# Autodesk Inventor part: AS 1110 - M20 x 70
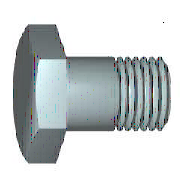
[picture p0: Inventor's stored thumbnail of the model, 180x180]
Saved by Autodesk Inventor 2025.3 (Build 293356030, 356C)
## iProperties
IsCustomPart: 0
Created: 2024-01
Part Number: AS 1110 - M20 x 70
Material: Acero, suave
Description: Pernos y tornillos métricos ISO de precisión de cabeza hexagonal
Document SubType Name: Modeling
Standard: AS 1110
Designer: User
Standards Organization: AS
Language: es-ES
Size Designation: M20 x 70
Categories: <MemberInstance><Categories><Category DisplayName="Fijaciones" InternalName="e4da775c-781d-43d5-af7c-5136215cf5a6" Mnemonic="FSTN"><Category DisplayName="Pernos
Density: 7.85 g/cm^3
Appearance: Semipulido
Author: User
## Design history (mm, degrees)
workplane "Work Plane1"
revolve "Cuerpo" stored, may be unused: angle "d12" = 90 deg
sketch "Boceto2"
  geometry: L1 (0, 17.321)-(15, 8.66); L2 (15, 8.66)-(15, -8.66); L3 (15, -8.66)-(0, -17.321); L4 (0, -17.321)-(-15, -8.66); L5 (-15, -8.66)-(-15, 8.66); L6 (-15, 8.66)-(0, 17.321); 2 further points
  constraints: 12 end point, 1 coincident, 1 vertical, 11 other
  dimensions: "d11" = 30 distance between parallel lines of L5 L2 (= SW)
extrude "Cabeza" join sketch "Boceto2" distance "d3" = 11.7 (= KOH - SD); taper "d4" = 0 deg
revolve "Chaflán1" stored, may be unused: angle "d21" = 90 deg
body "Solid1"
feature "Rosca" dims "d15" = 62.5 (= GEL), "d16" = 0
chamfer "Chaflán2" distance "d6" = 1.53363 (= -0.5 x SPD + 0.5 x GD); stored, may be unused: second distance "d7" = 1.53373 (computed from GUL), angle "d55" = 45 deg
sketch "Boceto1"
  geometry: L1 (0, 15)-(0, 10); L2 (7.5, 10)-(70, 10); L3 (70, 10)-(70, 0); L4 (70, 0)-(-0.8, 0); L5 (-14.96, 0)-(84.16, 0) reference; L6 (-0.8, 0)-(-0.8, 15); L7 (-0.8, 15)-(0, 15); L8 (7.5, 10)-(5.966, 10); L9 (5.966, 10)-(0, 10); L10 (0, -3)-(0, 18) reference
  constraints: 16 end point, 2 collinear, 2 perpendicular, 1 parallel
  dimensions: "d0" = 70 distance between parallel lines of L3 L1 (= NLG); "d1" = 62.5 distance from line of L2.start L3 (= GEL); "d2" = 20 diameter of L2 L4 (= GD); "d9" = 0.8001 distance between parallel lines of L6 L1 (computed from SD); "d10" = 30 diameter of L7 L4 (= SD2); "d13" = 1.53373 distance of L2.start L8.end (computed from GAL); "d14" = 20 diameter of L9 L4 (= BDM)
sketch "Boceto4"
  geometry: L1 (-12.5, 15)-(-12.5, 17.321); L2 (-12.5, 17.321)-(-11.16, 17.321); L3 (-11.16, 17.321)-(-12.5, 15); L4 (-14.84, 0)-(1.54, 0) reference; L5 (-0.8, 17.321)-(-12.5, 17.321) reference; L6 (-12.5, 8.66)-(-12.5, 17.321) reference
  constraints: 6 end point, 2 collinear, 1 perpendicular, 1 vertical
  dimensions: "d5" = 30 deg angle of L3 L1 (= ANG1); "d19" = 30 diameter of L1.start L4 (= SW0)
other parameters: "NLG" = 70 [user parameter; used in 1 equation term], "GD" = 20 (= NND) [user parameter; used in 2 equation terms], "BDM" = 20 (= NND) [user parameter; used in 1 equation term], "KOH" = 12.5 [user parameter; used in 1 equation term], "GEL" = 62.5 [user parameter; used in 2 equation terms], "SW" = 30 [user parameter; used in 5 equation terms], "SW0" = 30 (= SW) [user parameter; used in 1 equation term], "SPD" = 16.93275 (= NND - 1.2269 x PTC) [user parameter; used in 1 equation term], "SD2" = 30 (= SW) [user parameter; used in 1 equation term], "SD" = 0.8 [user parameter; used in 3 equation terms], "ANG1" = 30 deg [user parameter; used in 1 equation term], "GAL" = 1.53363 (= 0.61345 x PTC) [user parameter; used in 1 equation term], "GUL" = 1.53363 (= 0.61345 x PTC) [user parameter; used in 1 equation term], "d8" = 0, "RR" = 0.8 [user parameter], "d57" = 0, "d58" = 0, "TPU" = 4 (computed from PTC) [user parameter], "WFT" = 0.8 (= SD) [user parameter], "GD1" = 16.93275 (= THREADDIA - 1.2269 x PTC) [user parameter], "TOA" = 30 deg [user parameter], "FAWI" = 45 deg [user parameter], "PTC" = 2.5 [user parameter; used in 5 equation terms], "E0" = 34.65 (= 1.155 x SW) [user parameter]
